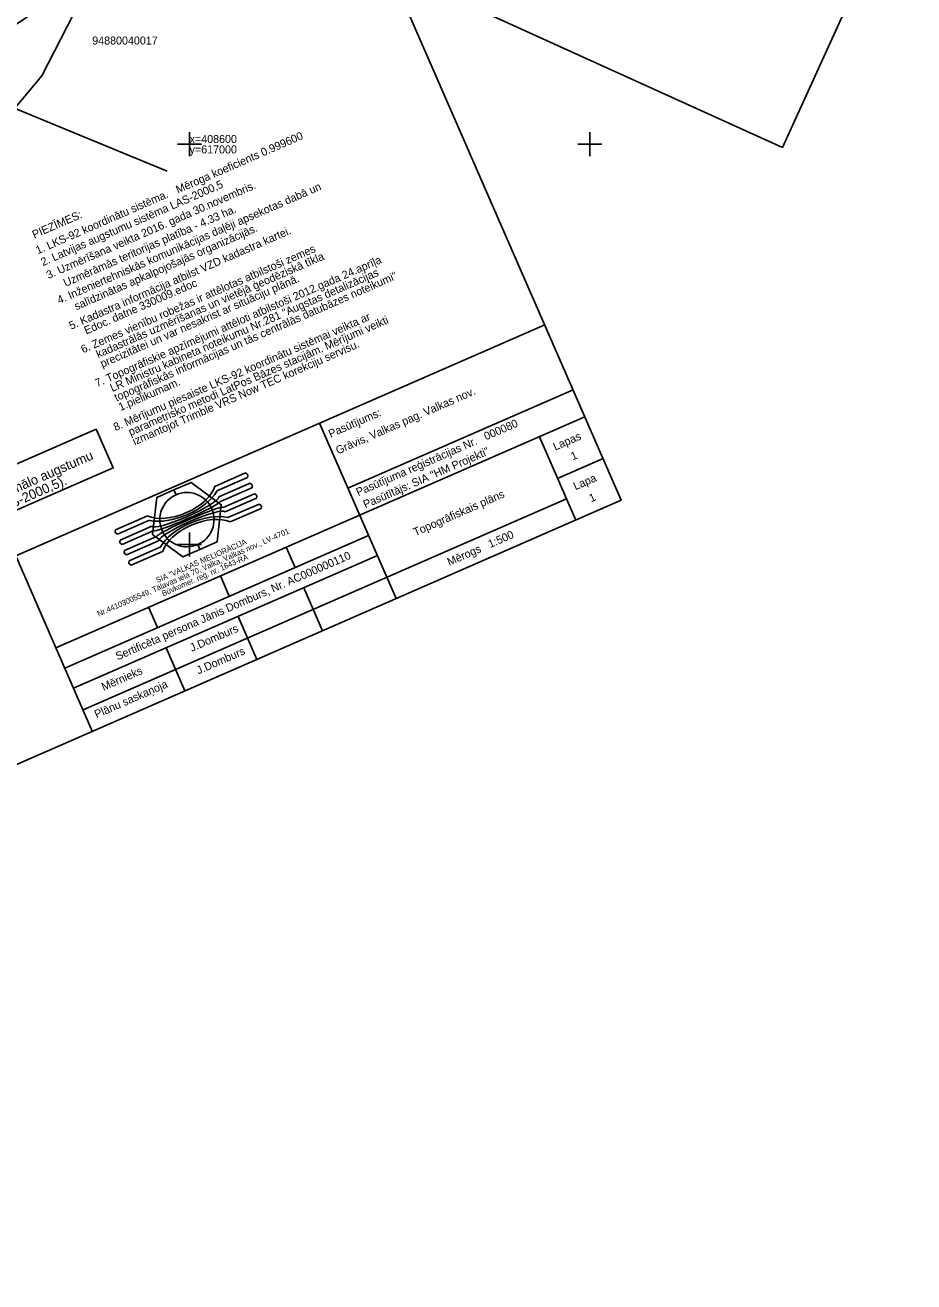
# Model space of a CAD drawing. Extents: x 616607 to 617499, y 408385 to 409695.
# Drawn here: x 616979.4 to 617090.5, y 408457.9 to 408614.9 of the extents above; entities that cross this region are included whole.
import ezdxf

# ---------------------------------------------------------------- set-up
doc = ezdxf.new("R2010")
doc.units = 0
for name, color, linetype in [('GEOD_ELEM_####_####_#', 7, 'Continuous'), ('GEOD_KORD_####_TKST_#', 7, 'Continuous'), ('Level 1', 7, 'Continuous'), ('Level 2', 7, 'Continuous'), ('RAMI_PLAN_####_TKST_#', 7, 'Continuous'), ('RAMI_UZMR_####_####_#', 7, 'Continuous'), ('RELJ_NOGA_####_####_#', 7, 'Continuous'), ('ROBZ_IERR_####_####_#', 7, 'Continuous'), ('ROBZ_IERR_####_TKST_#', 7, 'Continuous'), ('ROBZ_UZMR_####_####_#', 7, 'Continuous')]:
    doc.layers.add(name, color=color, linetype=linetype)

# ---------------------------------------------------------------- blocks, each defined once
blk = doc.blocks.new('KRUSTS')
at = {"layer": 'GEOD_ELEM_####_####_#'}
for p, q in [((-1.5, 0), (0, 0)), ((0, 1.5), (0, 0)), ((0, 0), (0, -1.5)), ((0, 0), (1.5, 0))]:
    blk.add_line(p, q, dxfattribs=at)
blk = doc.blocks.new('Logo')
at = {"layer": 'Level 1'}
for p, q in [((-1078, 277), (-1081, 266)), ((-1081, 266), (-1078, 253)), ((-1061, 299), (-1078, 277)), ((-1078, 253), (-1061, 227)), ((-544, 299), (-1061, 299)), ((-1061, 227), (-540, 227)), ((-540, 227), (-540, 223)), ((1054, 299), (555, 299)), ((555, 223), (555, 227)), ((555, 227), (1054, 227)), ((1071, 274), (1054, 299)), ((1054, 227), (1071, 249)), ((1074, 261), (1071, 274)), ((1071, 249), (1074, 261)), ((-1078, 109), (-1081, 97)), ((-1081, 97), (-1078, 84)), ((-1061, 131), (-1078, 109)), ((-1078, 84), (-1061, 59)), ((-544, 131), (-1061, 131)), ((-1061, 59), (-544, 59)), ((-544, 130), (-544, 131)), ((-544, 59), (-544, 59)), ((540, 58), (540, 59)), ((540, 59), (1054, 59)), ((1054, 131), (544, 131)), ((544, 131), (544, 130)), ((1071, 105), (1054, 131)), ((1054, 59), (1071, 81)), ((1074, 92), (1071, 105)), ((1071, 81), (1074, 92)), ((-1078, -60), (-1081, -71)), ((-1081, -71), (-1078, -84)), ((-1061, -38), (-1078, -60)), ((-1078, -84), (-1061, -109)), ((-543, -38), (-1061, -38)), ((-1061, -109), (-543, -109)), ((-543, -37), (-543, -38)), ((-543, -109), (-543, -109)), ((1054, -38), (541, -38)), ((541, -38), (541, -38)), ((544, -109), (544, -109)), ((544, -109), (1054, -109)), ((1071, -63), (1054, -38)), ((1054, -109), (1071, -87)), ((1074, -76), (1071, -63)), ((1071, -87), (1074, -76)), ((-1078, -228), (-1081, -240)), ((-1081, -240), (-1078, -253)), ((-1061, -206), (-1078, -228)), ((-1078, -253), (-1061, -278)), ((-548, -206), (-1061, -206)), ((-1061, -278), (-547, -278)), ((-548, -203), (-548, -206)), ((547, -206), (547, -202)), ((1054, -206), (547, -206)), ((550, -278), (1054, -278)), ((1071, -232), (1054, -206)), ((1054, -278), (1071, -256)), ((1074, -244), (1071, -232)), ((1071, -256), (1074, -244))]:
    blk.add_line(p, q, dxfattribs=at)
for centre, major_axis, ratio, start_param, end_param in [((4, 438), (-606, 4), 0.541463, 0.448589, 2.718476), ((4, 413), (-664, 5), 0.506421, 0.614889, 2.5546), ((0, 133), (544, 2), 0.149844, 3.15381, 6.227497), ((-2, 60), (543, 1), 0.072629, 3.142706, 6.213096), ((-2, -39), (543, 1), 0.071692, 0.008953, 3.063663), ((4, -392), (-664, 5), 0.50462, 3.756674, 5.696), ((4, -418), (-606, 4), 0.541463, 3.59403, 5.856221), ((0, -114), (544, 2), 0.151794, 0.035116, 3.063006)]:
    blk.add_ellipse(centre, major_axis=major_axis, ratio=ratio, start_param=start_param, end_param=end_param, dxfattribs=at)
at = {"layer": 'Level 2'}
for points in [[(-26, 416), (-26, 494), (-305, 494), (-584, 11), (-305, -472), (-26, -472)], [(-26, -395), (-26, -472), (253, -472), (532, 11), (253, 494), (-26, 494), (-26, 416)], [(-26, -472), (-26, -395)]]:
    blk.add_lwpolyline(points, dxfattribs=at)
for start, end in [(90, 270), (270, 90)]:
    blk.add_arc((-26, 11), 405, start, end, dxfattribs=at)

msp = doc.modelspace()

# ---------------------------------------------------------------- linework, layer by layer
at = {"layer": 'RAMI_PLAN_####_TKST_#'}
for p, q in [((617074.1, 408599.57), (617158.24, 408784.97)), ((616996.58, 408686.96), (617053.95, 408555.52)), ((616943.51, 408658.83), (617074.1, 408599.57)), ((616978.27, 408548.59), (617044.38, 408577.45)), ((617047.93, 408569.32), (617019.78, 408557.03)), ((616983.29, 408537.09), (617049.4, 408565.95)), ((617016.23, 408565.16), (617025.8, 408543.23)), ((617043.71, 408563.46), (617048.26, 408553.03)), ((617051.68, 408560.72), (617045.99, 408558.23)), ((616850.87, 408466.87), (617053.95, 408555.52)), ((616986.68, 408529.33), (617047.09, 408555.7)), ((616984.4, 408534.55), (617022.36, 408551.12)), ((617012.07, 408549.65), (617013.18, 408547.12)), ((616978.27, 408548.59), (616987.84, 408526.66)), ((616985.5, 408532.04), (617023.46, 408548.61)), ((617003.84, 408546.06), (617004.95, 408543.52)), ((617016.62, 408539.22), (617014.27, 408544.6)), ((616995.98, 408539.61), (616994.87, 408542.15)), ((617008.39, 408535.63), (617006.05, 408541.01)), ((616997.08, 408537.09), (616999.42, 408531.72))]:
    msp.add_line(p, q, dxfattribs=at)
msp.add_lwpolyline([(616958.56, 408551.4), (616988.34, 408564.4), (616990.45, 408559.57), (616960.67, 408546.57)], close=True, dxfattribs=at)
at = {"layer": 'RAMI_UZMR_####_####_#'}
msp.add_lwpolyline([(616666.43, 408467.69), (616675.53, 408457.88), (616687.23, 408463.36), (616723.89, 408465.77), (616753.55, 408507.23), (616948.28, 408568.83), (616981.53, 408608.53), (617014.56, 408672.89), (617101.57, 408748.25), (617213.47, 409074.04)], dxfattribs=at)
at = {"layer": 'RELJ_NOGA_####_####_#'}
for points in [[(616952.11, 408607.53), (616956.15, 408614.17), (616960.13, 408620.84), (616964.13, 408627.5), (616969.36, 408636.21), (616974.53, 408644.95), (616979.75, 408653.67), (616982.37, 408658.03), (616985.02, 408662.36), (616987.71, 408666.68), (616989.06, 408668.84), (616990.44, 408670.98), (616991.84, 408673.11), (616992.53, 408674.17), (616993.24, 408675.23), (616993.95, 408676.29), (616994.66, 408677.36), (616995.38, 408678.41), (616996.1, 408679.46), (616998.16, 408682.44), (617000.49, 408685.21), (617003.04, 408687.81), (617005.59, 408690.41), (617008.24, 408692.88), (617011.02, 408695.21), (617013.81, 408697.56), (617016.63, 408699.88), (617019.42, 408702.23), (617020.82, 408703.41), (617022.22, 408704.57), (617023.59, 408705.77), (617024.96, 408706.97), (617026.3, 408708.19), (617027.64, 408709.42), (617031.8, 408713.2), (617035.92, 408717.02), (617040.08, 408720.8), (617044.24, 408724.57), (617048.47, 408728.27), (617052.64, 408732.03), (617056.82, 408735.79), (617060.98, 408739.59), (617065.09, 408743.44), (617067.16, 408745.37), (617069.19, 408747.34), (617071.21, 408749.32), (617072.22, 408750.31), (617073.22, 408751.32), (617074.23, 408752.32), (617075.23, 408753.33), (617076.23, 408754.34), (617077.21, 408755.38), (617081.7, 408760.11), (617084.99, 408765.98), (617087.24, 408772.09), (617089.54, 408778.32), (617091.53, 408784.63), (617093.83, 408790.85), (617099.65, 408806.55), (617105.38, 408822.28), (617111.33, 408837.93), (617116.97, 408852.77), (617122.79, 408867.53), (617128.47, 408882.35), (617134.52, 408898.17), (617140.11, 408914.17), (617146.15, 408930), (617147.2, 408932.76), (617148.41, 408935.46), (617149.61, 408938.16), (617150.81, 408940.87), (617152.22, 408943.44), (617153.49, 408946.15), (617155.13, 408949.65), (617156.25, 408953.34), (617157.39, 408956.94), (617157.39, 408956.94), (617157.38, 408956.96), (617157.38, 408956.95), (617158.59, 408956.69), (617159.79, 408956.42), (617161, 408956.15)], [(617163.79, 408955.54), (617165.45, 408955.19), (617167.11, 408954.85), (617168.77, 408954.5), (617168.91, 408954.47), (617169.03, 408954.32), (617169.07, 408954.18), (617169.13, 408953.99), (617169.08, 408953.77), (617169.01, 408953.59), (617168.83, 408953.15), (617168.67, 408952.71), (617168.48, 408952.27), (617167.48, 408949.89), (617166.49, 408947.51), (617165.49, 408945.14), (617164.48, 408942.76), (617163.44, 408940.4), (617162.43, 408938.02), (617160.42, 408933.27), (617158.39, 408928.51), (617156.54, 408923.69), (617150.71, 408908.51), (617144.93, 408893.31), (617139.11, 408878.12), (617136.2, 408870.52), (617133.29, 408862.93), (617130.38, 408855.34), (617127.46, 408847.74), (617124.5, 408840.17), (617121.55, 408832.59), (617116.62, 408819.98), (617111.62, 408807.4), (617106.66, 408794.8), (617101.92, 408782.74), (617097.39, 408770.6), (617092.68, 408758.52), (617091.75, 408756.13), (617090.64, 408753.8), (617089.1, 408751.7), (617087.89, 408750.06), (617086.51, 408748.61), (617085.08, 408747.19), (617082.09, 408744.25), (617079.14, 408741.3), (617076.08, 408738.45), (617073.02, 408735.61), (617069.97, 408732.75), (617066.86, 408729.96), (617060.64, 408724.38), (617054.35, 408718.89), (617048.12, 408713.32), (617041.9, 408707.75), (617035.72, 408702.15), (617029.58, 408696.49), (617026.51, 408693.66), (617023.56, 408690.7), (617020.6, 408687.76), (617017.63, 408684.82), (617014.68, 408681.86), (617011.93, 408678.7), (617008.52, 408674.78), (617005.36, 408670.66), (617002.29, 408666.48), (616999.32, 408662.43), (616996.36, 408658.37), (616993.42, 408654.3), (616990.49, 408650.24), (616987.57, 408646.16), (616984.69, 408642.06), (616983.29, 408640.06), (616981.95, 408638.02), (616980.7, 408635.92), (616979.45, 408633.82), (616978.24, 408631.7), (616977.03, 408629.57), (616975.83, 408627.44), (616974.65, 408625.3), (616973.45, 408623.17), (616972.26, 408621.05), (616970.98, 408618.97), (616969.73, 408616.89), (616969.61, 408616.7), (616969.41, 408616.59), (616969.29, 408616.38), (616969, 408615.87), (616968.95, 408615.29), (616969.02, 408614.76), (616969.09, 408614.25), (616969.19, 408613.68), (616969.49, 408613.25)]]:
    msp.add_open_spline(points, degree=3, dxfattribs=at)
at = {"layer": 'ROBZ_IERR_####_####_#'}
msp.add_lwpolyline([(616997.18, 408596.64), (616974.84, 408605.83), (616968.57, 408608.4), (616998.91, 408628.92)], dxfattribs=at)
at = {"layer": 'ROBZ_UZMR_####_####_#'}
msp.add_lwpolyline([(616705, 408460.63), (616695.31, 408466.84), (616688.05, 408471.5), (616708.65, 408488.2), (616730.49, 408522.34), (616805.46, 408543.66), (616889.79, 408568.01), (616940.58, 408582.8), (616958.52, 408604.59), (616968.57, 408608.4), (616974.84, 408605.83), (616993.23, 408598.27)], dxfattribs=at)

# ---------------------------------------------------------------- block references
at = {"layer": 'GEOD_ELEM_####_####_#'}
for p in [(617000, 408600), (617050, 408600), (617000, 408550)]:
    msp.add_blockref('KRUSTS', p, dxfattribs=at)
at = {"layer": 'Level 2', "xscale": 0.008375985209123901, "yscale": 0.008375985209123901, "rotation": 23.582113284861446}
msp.add_blockref('Logo', (616999.9, 408553.1), dxfattribs=at)

# ---------------------------------------------------------------- texts
at = {"layer": 'GEOD_KORD_####_TKST_#'}
for s, p in [('x=408600', (617000, 408600.15)), ('y=617000', (617000, 408598.85))]:
    msp.add_text(s, height=1, dxfattribs=at).set_placement(p)
at = {"layer": 'RAMI_PLAN_####_TKST_#'}
for s, height, rotation, p in [('Mēroga koeficients 0.999600', 1, 23.5821, (616998.54, 408593.82)), ('2. Latvijas augstumu sistēma LAS-2000,5', 1, 23.5821, (616981.67, 408584.76)), ('3. Uzmērīšana veikta 2016. gada 30.novembris.', 1, 23.5821, (616982.36, 408583.15)), ('4. Inženiertehniskās komunikācijas daļēji apsekotas dabā un ', 1, 23.5821, (616983.71, 408580.02)), ('1. LKS-92 koordinātu sistēma. ', 1, 23.5821, (616981.03, 408586.23)), ('PIEZĪMES:', 1, 23.5821, (616980.59, 408588.2)), ('Uzmērāmās teritorijas platība - 4.33 ha.', 1, 23.5821, (616984.49, 408582.17)), ('5. Kadastra informācija atbilst VZD kadastra kartei.', 1, 23.5821, (616985.2, 408576.81)), ('salīdzinātas apkalpojošajās organizācijās.', 1, 23.5821, (616985.84, 408579.24)), ('6. Zemes vienību robežas ir attēlotas atbilstoši zemes', 1, 23.5821, (616986.69, 408573.86)), ('7. Topogrāfiskie apzīmējumi attēloti atbilstoši 2012.gada 24.aprīļa ', 1, 23.5821, (616988.45, 408569.64)), ('    kadastrālās uzmērīšanas un vietējā ģeodēziskā tīkla ', 1, 23.5821, (616987.21, 408572.67)), ('    precizitātei un var nesakrist ar situāciju plānā.', 1, 23.5821, (616987.73, 408571.48)), ('    LR Ministru kabineta noteikumu Nr.281 "Augstas detalizācijas', 1, 23.5821, (616988.97, 408568.44)), ('    topogrāfiskās informācijas un tās centrālās datubāzes noteikumi" ', 1, 23.5821, (616989.49, 408567.25)), ('    Edoc. datne 330009.edoc', 1, 23.5821, (616985.72, 408575.62)), ('8. Mērījumu piesaiste LKS-92 koordinātu sistēmai veikta ar ', 1, 23.5821, (616990.74, 408564.15)), ('    parametrisko metodi LatPos Bāzes stacijām. Mērījumi veikti ', 1, 23.5821, (616991.25, 408562.96)), ('    izmantojot Trimble VRS Now TEC korekciju servisu.', 1, 23.5821, (616991.77, 408561.78)), ('    1.pielikumam.', 1, 23.5821, (616990.01, 408566.06)), ('Grāvis, Valkas pag. Valkas nov.', 1, 23.5817, (617018.53, 408561.24)), ('Pasūtījums:', 1, 23.5817, (617017.62, 408563.31)), ('000080', 1, 23.5817, (617037.05, 408562.99)), ('Pasūtījuma reģistrācijas Nr.', 1, 23.5817, (617021.07, 408556.02)), ('Lapas', 1, 23.5817, (617045.69, 408561.71)), ('Plāns sastādīts Latvijas normālo augstumu', 1.2, 23.5821, (616960.12, 408548.49)), ('Pasūtītājs: SIA "HM Projekti"', 1, 23.5817, (617021.96, 408554.49)), ('1', 1, 23.5817, (617047.89, 408560.49)), ('sistēmā epohā 2000,5 (LAS-2000,5).', 1.2, 23.5821, (616960.74, 408547.06)), ('Lapa', 1, 23.5817, (617048.22, 408556.76)), ('Topogrāfiskais plāns', 1, 23.5817, (617028.21, 408551.03)), ('1', 1, 23.5817, (617050.18, 408555.26)), ('Nr.44103005549, Tālavas iela 70, Valka, Valkas nov., LV-4701', 0.7, 23.5821, (616988.64, 408540.98)), ('SIA "VALKAS MELIORĀCIJA', 0.7, 23.5821, (616995.98, 408545.17)), ('Mērogs   1:500', 1, 23.5817, (617032.45, 408547.31)), ('Sertificēta persona Jānis Domburs, Nr. AC000000110', 1, 23.5821, (616991.02, 408535.51)), ('Būvkomer. reģ. nr. 1643-RA', 0.7, 23.5821, (616996.7, 408543.51)), ('J.Domburs', 1, 23.5821, (617000.28, 408536.57)), ('J.Domburs', 1, 23.5821, (617001.11, 408533.75)), ('Mērnieks', 1, 23.5817, (616989.25, 408531.7)), ('Plānu saskaņoja', 1, 23.5817, (616988.37, 408528.27))]:
    msp.add_text(s, height=height, rotation=rotation, dxfattribs=at).set_placement(p)
at = {"layer": 'ROBZ_IERR_####_TKST_#'}
msp.add_text('94880040017', height=1, dxfattribs=at).set_placement((616987.83, 408612.45))

doc.saveas('drawing.dxf')
